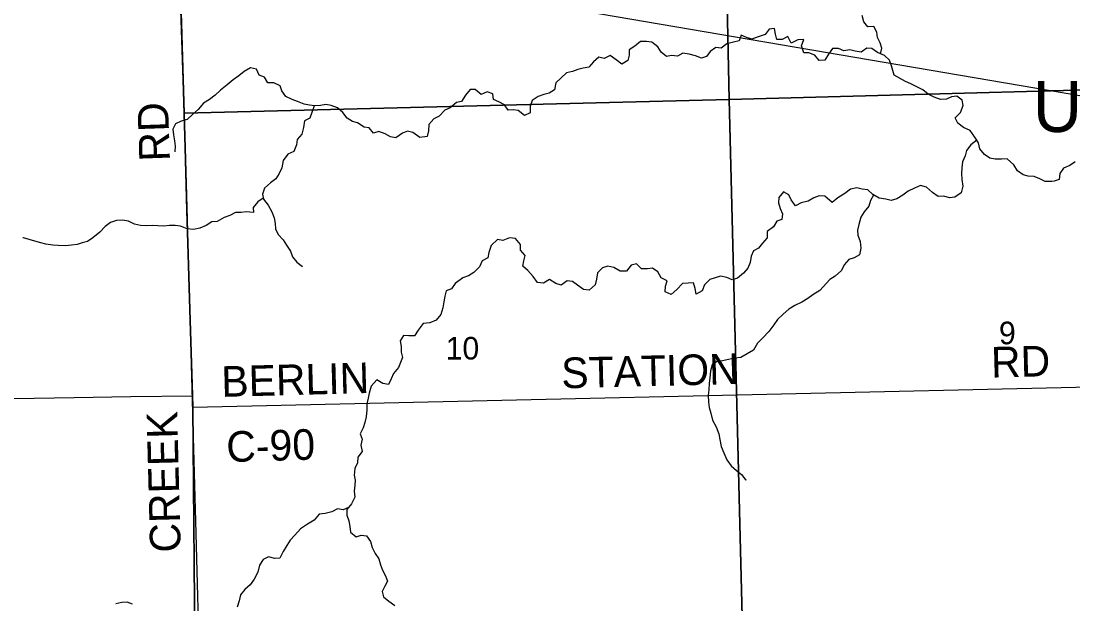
# Model space of a CAD drawing. Extents: x 0 to 34, y 0 to 22.
# Drawn here: x 6.483 to 8.435, y 11.927 to 13.008 of the extents above; entities that cross this region are included whole.
import ezdxf

# ---------------------------------------------------------------- set-up
doc = ezdxf.new("R2010")
doc.units = 0
for name, color, linetype in [('GM_X_Corporation', 7, 'Continuous'), ('GM_X_County_Road', 7, 'Continuous'), ('GM_X_County_Road_Text', 7, 'Continuous'), ('GM_X_Minor_Lake_Text', 7, 'Continuous'), ('GM_X_Minor_River', 7, 'Continuous'), ('GM_X_Section_Text', 7, 'Continuous'), ('GM_X_Township_Road', 7, 'Continuous'), ('SH_Text', 7, 'Continuous')]:
    doc.layers.add(name, color=color, linetype=linetype)

msp = doc.modelspace()

# ---------------------------------------------------------------- linework, layer by layer
at = {"layer": 'GM_X_Corporation'}
for points in [[(6.7793, 13.0289), (6.7835, 12.8989), (6.7875, 12.7733), (6.7907, 12.6568), (6.7962, 12.4725), (6.8009, 12.313), (6.8013, 12.2922), (6.8061, 11.7851), (6.8093, 11.6831), (6.8339, 10.7907), (7.8767, 10.8135), (8.3328, 10.8251), (9.3392, 10.8506), (9.4256, 10.8527), (9.5231, 10.8551), (9.5231, 15.9621)], [(5.571, 10.7686), (6.8097, 10.7901), (6.8339, 10.7907), (6.8093, 11.6831), (6.8061, 11.7851), (6.8013, 12.2922), (6.8009, 12.313), (6.7962, 12.4725), (6.7907, 12.6568), (6.7875, 12.7733), (6.7835, 12.8989), (6.7793, 13.0289)]]:
    msp.add_lwpolyline(points, dxfattribs=at)
for points in [[(8.7817, 13.9109), (8.8081, 12.8893), (7.797, 12.8624), (7.775, 13.8905)], [(7.775, 13.8905), (7.797, 12.8624), (6.7858, 12.8368), (6.7722, 13.2952), (6.7607, 13.8687)], [(8.8081, 12.8893), (8.8368, 11.8577), (7.823, 11.8291), (7.797, 12.8624)], [(7.797, 12.8624), (7.823, 11.8291), (6.8147, 11.8013), (6.8075, 12.0575), (6.7905, 12.6841), (6.7858, 12.8368)]]:
    msp.add_lwpolyline(points, close=True, dxfattribs=at)
at = {"layer": 'GM_X_County_Road'}
for points in [[(6.8063, 11.7845), (6.8015, 12.2917), (6.8011, 12.3125), (6.7964, 12.472), (6.7909, 12.6562), (6.7877, 12.7728), (6.7837, 12.8984), (6.7795, 13.0284), (6.7765, 13.1386), (6.773, 13.2414), (6.7717, 13.2976), (6.7432, 14.7769)], [(6.8015, 12.2917), (8.4398, 12.3285), (8.5985, 12.3319), (8.8852, 12.3415), (8.9734, 12.3441), (9.0963, 12.3476), (9.2173, 12.3542), (9.3204, 12.3571)]]:
    msp.add_lwpolyline(points, dxfattribs=at)
at = {"layer": 'GM_X_Minor_River'}
for points in [[(8.0779, 12.9471), (8.0799, 12.9574), (8.0768, 12.9672), (8.0721, 12.9771), (8.0705, 12.9873), (8.0655, 12.9975), (8.0544, 12.9967), (8.0464, 13.0065), (8.0436, 13.0179)], [(8.3958, 12.7099), (8.3833, 12.7104), (8.3733, 12.7153), (8.363, 12.7194), (8.3516, 12.7201), (8.3421, 12.7223), (8.3321, 12.7298), (8.3252, 12.7411), (8.3126, 12.752), (8.3023, 12.7516), (8.2905, 12.7515), (8.2806, 12.7537), (8.2706, 12.7605), (8.2622, 12.7707), (8.2594, 12.782), (8.2525, 12.7926), (8.244, 12.8047), (8.2318, 12.8103), (8.2214, 12.8186), (8.2164, 12.8284), (8.2262, 12.8384), (8.2311, 12.851), (8.2294, 12.8609), (8.2195, 12.8684), (8.2096, 12.8672), (8.1998, 12.8629), (8.1891, 12.8621), (8.1769, 12.8665), (8.1662, 12.8721), (8.1559, 12.88), (8.1452, 12.886), (8.1337, 12.8913), (8.1238, 12.8954), (8.1031, 12.9074), (8.098, 12.9248), (8.0945, 12.9354), (8.0849, 12.9441), (8.072, 12.9497), (8.0616, 12.9568), (8.0521, 12.9575), (8.0419, 12.9498), (8.0305, 12.952), (8.0206, 12.9546), (8.0096, 12.9522), (7.9996, 12.9567), (7.9886, 12.957), (7.9811, 12.9463), (7.9744, 12.9349), (7.9641, 12.9348), (7.9556, 12.9446), (7.9449, 12.9487), (7.9351, 12.949), (7.9311, 12.9615), (7.9356, 12.9733), (7.9242, 12.9732), (7.9117, 12.967), (7.9055, 12.9792), (7.8949, 12.9734), (7.885, 12.9733), (7.8826, 12.9835), (7.8807, 12.9938), (7.8712, 12.9929), (7.8633, 12.9826), (7.8507, 12.9787), (7.839, 12.9744), (7.8287, 12.9774), (7.8191, 12.9815), (7.8154, 12.9712), (7.8048, 12.9685), (7.7927, 12.9657), (7.7821, 12.9576), (7.7718, 12.9587), (7.7616, 12.9514), (7.7548, 12.9418), (7.7453, 12.9391), (7.7343, 12.9432), (7.7228, 12.9465), (7.711, 12.948), (7.7008, 12.9429), (7.6898, 12.9436), (7.6803, 12.942), (7.6707, 12.9499), (7.6642, 12.9598), (7.6531, 12.9684), (7.6432, 12.9695), (7.6321, 12.9701), (7.6219, 12.9613), (7.611, 12.9544), (7.6114, 12.9445), (7.6085, 12.9346), (7.5979, 12.9277), (7.5868, 12.9356), (7.5761, 12.9438), (7.5651, 12.9384), (7.5552, 12.941), (7.545, 12.9322), (7.5363, 12.9219), (7.5257, 12.9203), (7.5158, 12.9179), (7.5063, 12.9144), (7.4949, 12.9117)], [(7.4949, 12.9117), (7.4753, 12.8933), (7.4728, 12.8803), (7.463, 12.8741), (7.4527, 12.8714), (7.4421, 12.8675), (7.4311, 12.8606), (7.4278, 12.8492), (7.4275, 12.8378), (7.4169, 12.8324), (7.4054, 12.8421), (7.3959, 12.8428), (7.3864, 12.8424), (7.3798, 12.8522), (7.3692, 12.8578), (7.3592, 12.8623), (7.3584, 12.8729), (7.3477, 12.8766), (7.3367, 12.8716), (7.3256, 12.8807), (7.3161, 12.881), (7.3074, 12.8703), (7.3003, 12.8588), (7.2908, 12.8564), (7.2791, 12.8465), (7.2689, 12.8422), (7.2587, 12.8311), (7.2485, 12.8264), (7.2394, 12.8157), (7.2388, 12.8039), (7.2362, 12.7937), (7.2225, 12.7917), (7.2099, 12.8011), (7.2, 12.8033), (7.1905, 12.8001), (7.1784, 12.7913), (7.1685, 12.7931), (7.1582, 12.7984), (7.1468, 12.8028), (7.1369, 12.7997), (7.1288, 12.8099), (7.1193, 12.811), (7.1074, 12.8189), (7.0979, 12.8214), (7.088, 12.8274), (7.0799, 12.838), (7.0703, 12.8467), (7.0585, 12.8512), (7.0486, 12.853), (7.0383, 12.8514), (7.0277, 12.8505), (7.0182, 12.8516), (7.0079, 12.8538), (6.996, 12.8583), (6.9857, 12.862), (6.9743, 12.8676), (6.9666, 12.8782), (6.9638, 12.8877), (6.9516, 12.8929), (6.941, 12.8932), (6.9344, 12.9038), (6.9249, 12.9075), (6.9194, 12.9185), (6.9084, 12.9207), (6.8967, 12.9141), (6.8868, 12.9064), (6.8763, 12.8987), (6.8653, 12.8895), (6.8532, 12.8796), (6.8427, 12.8703), (6.8325, 12.8623), (6.8211, 12.8553), (6.8117, 12.8439), (6.8011, 12.8347), (6.7909, 12.8251), (6.7799, 12.8223), (6.7693, 12.8169), (6.7645, 12.807), (6.7657, 12.7968), (6.7677, 12.7857), (6.7689, 12.7759), (6.7683, 12.766), (6.7679, 12.7652)], [(7.0268, 12.8506), (7.0221, 12.8383), (7.0187, 12.8277), (7.0089, 12.8226), (7.0071, 12.8105), (7.0038, 12.7979), (6.9951, 12.7883), (6.9937, 12.778), (6.9892, 12.7655), (6.9779, 12.7608), (6.9689, 12.749), (6.9667, 12.7356), (6.9618, 12.725), (6.9555, 12.7154), (6.9456, 12.7077), (6.9343, 12.6981), (6.931, 12.6867), (6.9326, 12.6772), (6.9411, 12.6663), (6.9484, 12.6541), (6.9523, 12.6428), (6.9543, 12.6321), (6.9551, 12.6223), (6.9598, 12.612), (6.9694, 12.6019), (6.9756, 12.592), (6.9825, 12.5807), (6.9864, 12.5704), (6.9945, 12.5606), (7.0048, 12.5524)], [(8.2564, 12.7866), (8.245, 12.7781), (8.2375, 12.7678), (8.2345, 12.7579), (8.2297, 12.7465), (8.2286, 12.7354), (8.228, 12.7251), (8.2288, 12.7141), (8.2301, 12.7016), (8.2275, 12.6894), (8.2158, 12.681), (8.2059, 12.6801), (8.1949, 12.6831), (8.1846, 12.6826), (8.1739, 12.6898), (8.1632, 12.6999), (8.1517, 12.7025), (8.1404, 12.6978), (8.129, 12.6921), (8.1192, 12.6848), (8.1078, 12.6778), (8.0972, 12.6751), (8.0873, 12.6773), (8.0751, 12.6791), (8.0636, 12.6858), (8.0541, 12.6945), (8.0434, 12.6959), (8.0339, 12.6985), (8.0217, 12.6961), (8.0115, 12.6881), (7.9987, 12.6796), (7.9881, 12.6712), (7.9743, 12.6832), (7.964, 12.6835), (7.9542, 12.68), (7.9432, 12.6739), (7.9303, 12.6703), (7.9201, 12.6649), (7.9116, 12.6759), (7.9077, 12.6857), (7.8974, 12.691), (7.8887, 12.6803), (7.8884, 12.6708), (7.8912, 12.6598), (7.8958, 12.6499), (7.8948, 12.6396), (7.8853, 12.6365), (7.8789, 12.6258), (7.8672, 12.6174), (7.8673, 12.6056), (7.8587, 12.596), (7.8515, 12.5865), (7.8417, 12.5818), (7.8376, 12.5719), (7.8358, 12.5601), (7.8317, 12.5494), (7.8234, 12.5399), (7.8125, 12.531), (7.8026, 12.5275), (7.7923, 12.5324), (7.7805, 12.5346), (7.771, 12.5315), (7.7611, 12.5283), (7.7513, 12.5184), (7.7469, 12.5073), (7.7355, 12.5012), (7.7339, 12.5114), (7.7308, 12.522), (7.7209, 12.5216), (7.7102, 12.5207), (7.6997, 12.5096), (7.6891, 12.5008), (7.678, 12.5056), (7.6787, 12.5159), (7.6817, 12.5262), (7.6706, 12.5318), (7.6644, 12.5424), (7.6545, 12.5495), (7.645, 12.5479), (7.6343, 12.5479), (7.6247, 12.5573), (7.6152, 12.5549), (7.6062, 12.5438), (7.5948, 12.5437), (7.5829, 12.5509), (7.5719, 12.5531), (7.5616, 12.5503), (7.5526, 12.5408), (7.5504, 12.5293), (7.5479, 12.5183), (7.5373, 12.5087), (7.5262, 12.5098), (7.5155, 12.5176), (7.506, 12.5248), (7.4961, 12.5262), (7.4851, 12.5182), (7.4752, 12.5207), (7.4637, 12.5283), (7.4524, 12.5217), (7.4409, 12.5231), (7.4332, 12.5341)], [(8.4388, 12.7465), (8.4287, 12.7396), (8.417, 12.7349), (8.4103, 12.7253), (8.4094, 12.7139), (8.3996, 12.7107), (8.3958, 12.7099)], [(6.9323, 12.679), (6.922, 12.6722), (6.9137, 12.6622), (6.9142, 12.6527), (6.9005, 12.6541), (6.891, 12.6526), (6.8807, 12.6525), (6.8701, 12.6471), (6.8599, 12.6436), (6.847, 12.6362), (6.8367, 12.6354), (6.8265, 12.6285), (6.8148, 12.6234), (6.803, 12.6214), (6.7912, 12.6221), (6.7786, 12.6273), (6.7687, 12.6284), (6.7581, 12.6287), (6.7478, 12.6271), (6.7368, 12.6281), (6.7265, 12.6288), (6.7151, 12.628), (6.7044, 12.6283), (6.6934, 12.6312), (6.6823, 12.6368), (6.6713, 12.6386), (6.6599, 12.6378), (6.6489, 12.6339), (6.6387, 12.6266), (6.6292, 12.6159), (6.616, 12.6055), (6.6058, 12.5986), (6.5963, 12.5962), (6.5868, 12.5935), (6.5766, 12.5919), (6.5652, 12.5907), (6.5515, 12.5917), (6.542, 12.592), (6.529, 12.5942), (6.5195, 12.5967), (6.5084, 12.5997), (6.4978, 12.6023), (6.4871, 12.6056), (6.4863, 12.6056)], [(8.0649, 12.6851), (8.0588, 12.6752), (8.0558, 12.6641), (8.0472, 12.6538), (8.0412, 12.6438), (8.0371, 12.6301), (8.0349, 12.6202), (8.0354, 12.6107), (8.0401, 12.599), (8.0409, 12.5864), (8.0384, 12.5743), (8.0285, 12.5685), (8.0191, 12.5657), (8.01, 12.5554), (8.0052, 12.5451), (7.9935, 12.5348), (7.9833, 12.5282), (7.9652, 12.5083), (7.9523, 12.4998), (7.9425, 12.4933), (7.9319, 12.4864), (7.9186, 12.4802), (7.9073, 12.4733), (7.8967, 12.4644), (7.8865, 12.4541), (7.8798, 12.4445), (7.8704, 12.4319), (7.8591, 12.4204), (7.8493, 12.4101), (7.8418, 12.3975), (7.83, 12.3905), (7.8187, 12.384), (7.8069, 12.3824), (7.7955, 12.38), (7.7845, 12.3776), (7.775, 12.3772), (7.7652, 12.3703), (7.7619, 12.3588), (7.7612, 12.3455), (7.7594, 12.336), (7.7591, 12.3235), (7.7577, 12.3139), (7.7582, 12.301), (7.7598, 12.2908), (7.7629, 12.2805), (7.7661, 12.2676), (7.7727, 12.2551), (7.7777, 12.2423), (7.7793, 12.2316), (7.7821, 12.2187), (7.7868, 12.207), (7.7926, 12.1937), (7.8003, 12.1831), (7.8103, 12.1741), (7.8198, 12.1666), (7.8279, 12.1564), (7.8283, 12.1579)], [(7.4332, 12.5341), (7.4232, 12.545), (7.4137, 12.5529), (7.4159, 12.5632), (7.4181, 12.5731), (7.4096, 12.5829), (7.4095, 12.5936), (7.4003, 12.6042), (7.3889, 12.6056), (7.3767, 12.6005), (7.3668, 12.6028), (7.3551, 12.5916), (7.3507, 12.5787), (7.3489, 12.5688), (7.3383, 12.563), (7.3338, 12.5519), (7.3229, 12.5412), (7.313, 12.535), (7.3024, 12.5312), (7.2881, 12.5208), (7.2817, 12.5108), (7.2714, 12.5073), (7.2689, 12.4974), (7.2674, 12.4868), (7.2653, 12.4761), (7.2616, 12.4632), (7.2529, 12.4528), (7.2412, 12.4478), (7.229, 12.4466), (7.2196, 12.4343), (7.2128, 12.424), (7.2022, 12.4239), (7.1923, 12.4246), (7.1863, 12.4147), (7.1879, 12.4044), (7.1884, 12.3938), (7.1908, 12.3835), (7.1829, 12.3652), (7.1739, 12.3541), (7.1698, 12.3442), (7.1646, 12.3335), (7.1539, 12.3354), (7.1428, 12.3425), (7.1327, 12.3303), (7.1286, 12.3177), (7.1268, 12.3082), (7.1246, 12.2979), (7.1247, 12.2865), (7.1233, 12.2735), (7.1207, 12.2633), (7.1174, 12.2533), (7.1121, 12.2423), (7.116, 12.2324), (7.1131, 12.2214), (7.1155, 12.2096), (7.108, 12.1989), (7.1069, 12.1886), (7.1021, 12.178), (7.101, 12.1658), (7.1026, 12.1563), (7.1019, 12.1468), (7.1009, 12.1361), (7.1021, 12.1248), (7.0962, 12.1125), (7.0875, 12.1018), (7.0872, 12.0916), (7.0911, 12.081), (7.0931, 12.0703), (7.0943, 12.0601), (7.1047, 12.0514), (7.1142, 12.0541), (7.1237, 12.0527), (7.131, 12.0425), (7.1341, 12.0315), (7.1396, 12.0205), (7.1469, 12.0103), (7.1496, 11.9989), (7.1532, 11.9891), (7.1593, 11.9789), (7.1628, 11.969), (7.1576, 11.9595), (7.1531, 11.9496), (7.1551, 11.9401), (7.1654, 11.9318), (7.1762, 11.9239)], [(7.0904, 12.1054), (7.0803, 12.101), (7.07, 12.1028), (7.0594, 12.0978), (7.0473, 12.0943), (7.0359, 12.0934), (7.0268, 12.082), (7.0143, 12.0746), (7.0015, 12.0658), (6.9906, 12.0543), (6.9823, 12.0447), (6.9759, 12.0348), (6.9691, 12.0237), (6.9632, 12.0115), (6.9537, 12.0111), (6.9422, 12.014), (6.932, 12.0094), (6.9253, 11.9983), (6.9219, 11.9853), (6.9152, 11.9727), (6.9081, 11.9624), (6.8983, 11.9536), (6.89, 11.9433), (6.8874, 11.9322), (6.8837, 11.9204)], [(6.6897, 11.9265), (6.6794, 11.9302), (6.6695, 11.9293), (6.6585, 11.9266)]]:
    msp.add_lwpolyline(points, dxfattribs=at)
at = {"layer": 'GM_X_Township_Road'}
msp.add_lwpolyline([(6.3947, 12.3066), (6.5814, 12.3097), (6.6865, 12.3116), (6.8011, 12.3125)], dxfattribs=at)
at = {"layer": 'SH_Text'}
msp.add_lwpolyline([(10.1431, 12.8377), (5.8618, 13.3103), (10.1431, 12.581)], close=True, dxfattribs=at)

# ---------------------------------------------------------------- texts
at = {"layer": 'GM_X_County_Road_Text'}
for s, rotation, p in [('RD', 91.9757, (6.7592, 12.7483)), ('RD', 1.4806, (8.2834, 12.3464)), ('STATION', 1.4486, (7.486, 12.3264)), ('BERLIN', 1.5223, (6.8551, 12.3106)), ('CREEK', 91.4688, (6.7792, 12.0227)), ('C-90', 1.714, (6.8645, 12.1896))]:
    msp.add_text(s, height=0.05682, rotation=rotation, dxfattribs=at).set_placement(p)
at = {"layer": 'GM_X_Minor_Lake_Text'}
msp.add_text('Upper Diehl', height=0.094732, rotation=359.9569, dxfattribs=at).set_placement((8.3602, 12.802))
at = {"layer": 'GM_X_Section_Text'}
for s, height, p in [('9', 0.0419, (8.2974, 12.4083)), ('10', 0.04186, (7.2707, 12.38))]:
    msp.add_text(s, height=height, rotation=0, dxfattribs=at).set_placement(p)

doc.saveas('drawing.dxf')
